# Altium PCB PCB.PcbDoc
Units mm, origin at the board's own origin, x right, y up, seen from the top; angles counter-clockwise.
Board outline 43.18 x 17.78 mm, 4 copper layers (TOP, GND, SIG, BOTTOM), stack 1.586 mm thick; 58 components, 50 nets, 295 pads, 112 vias.
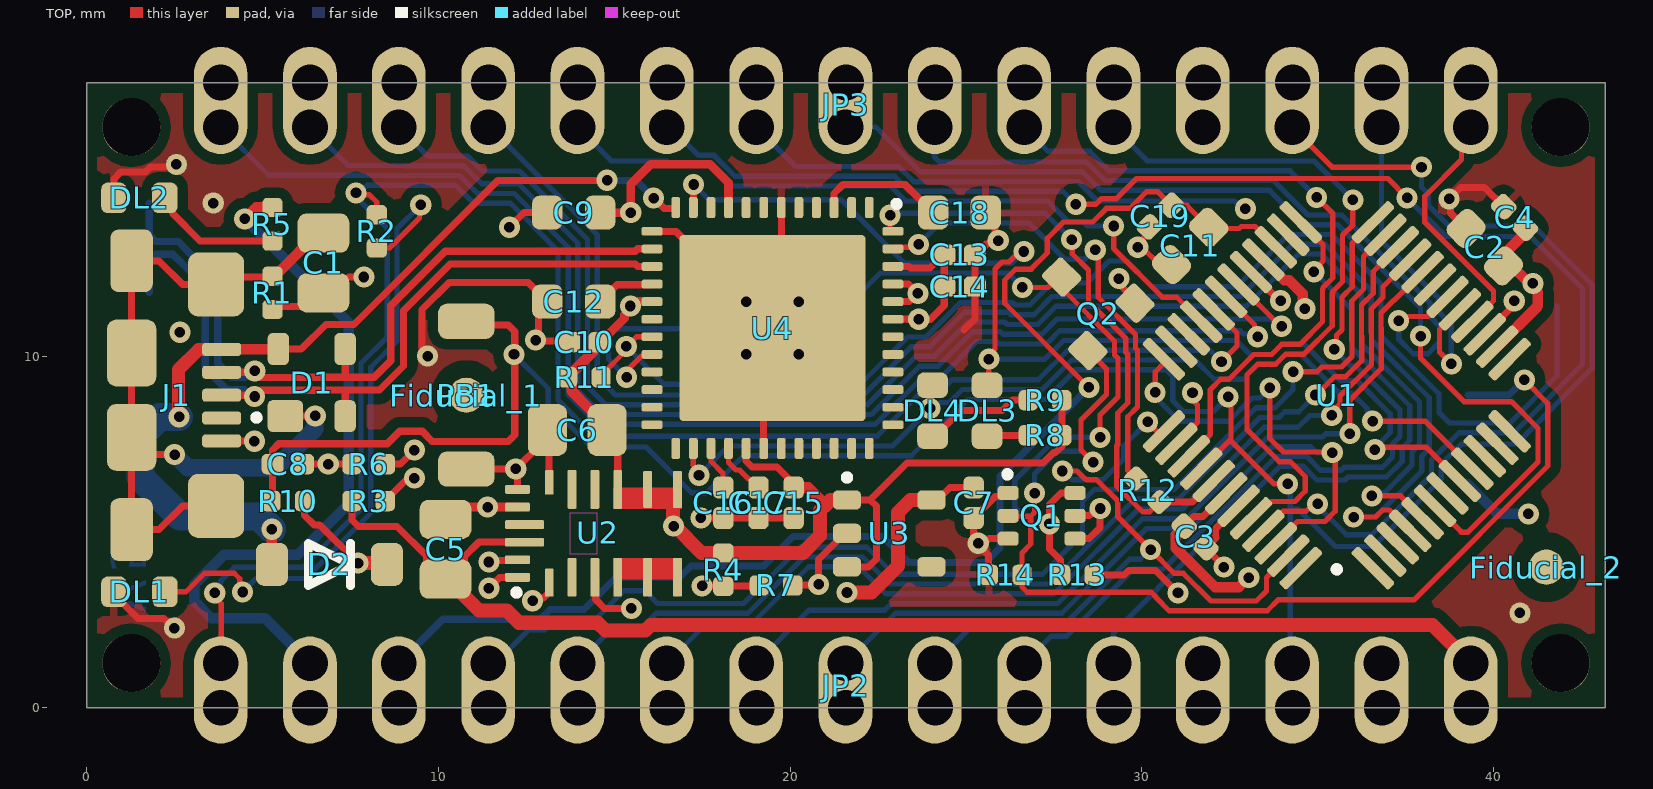
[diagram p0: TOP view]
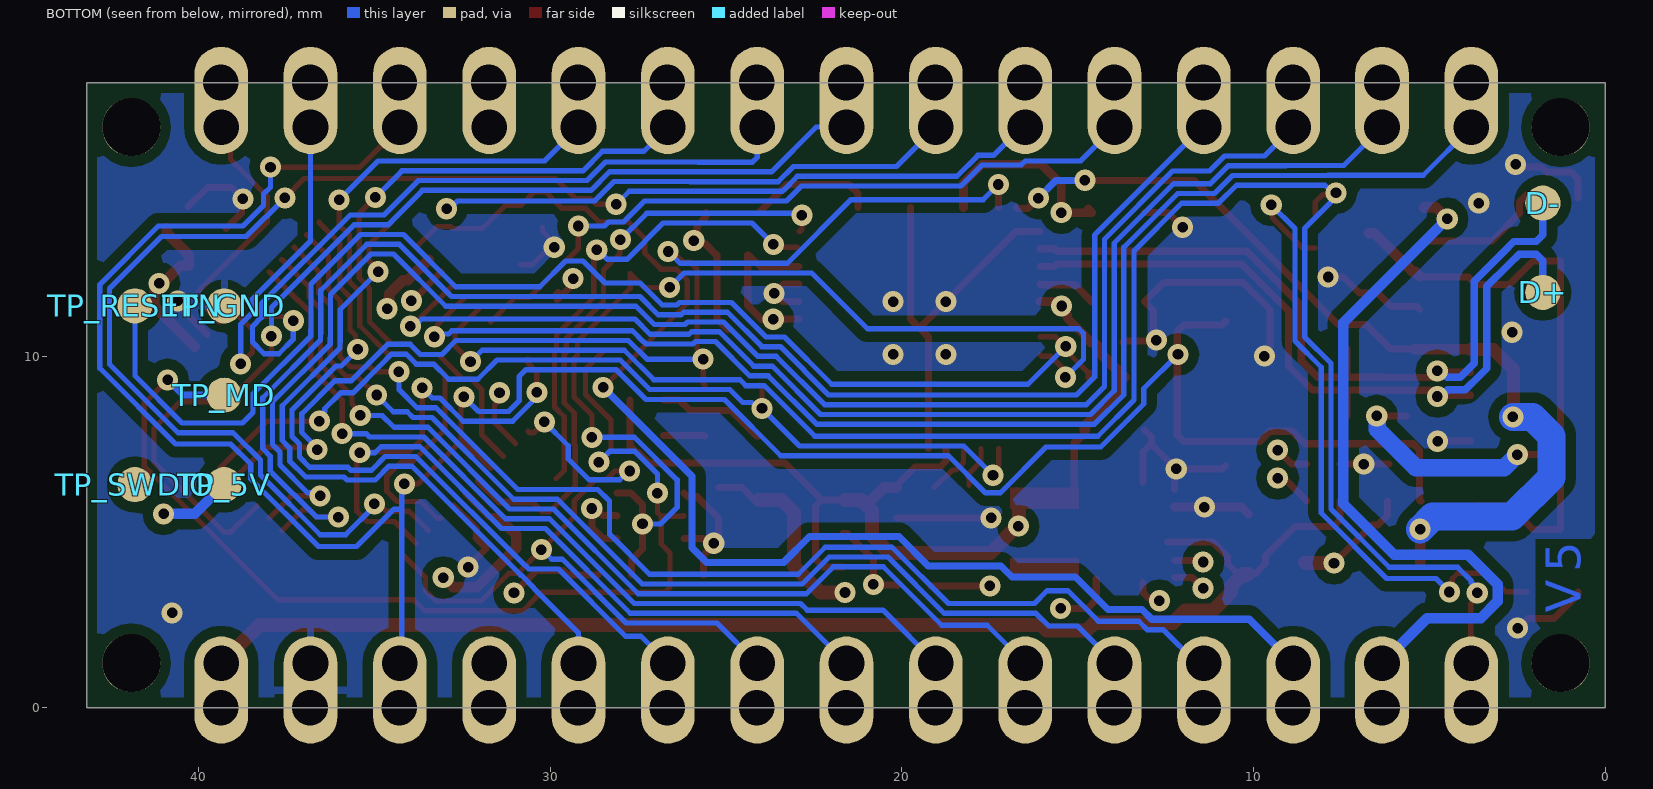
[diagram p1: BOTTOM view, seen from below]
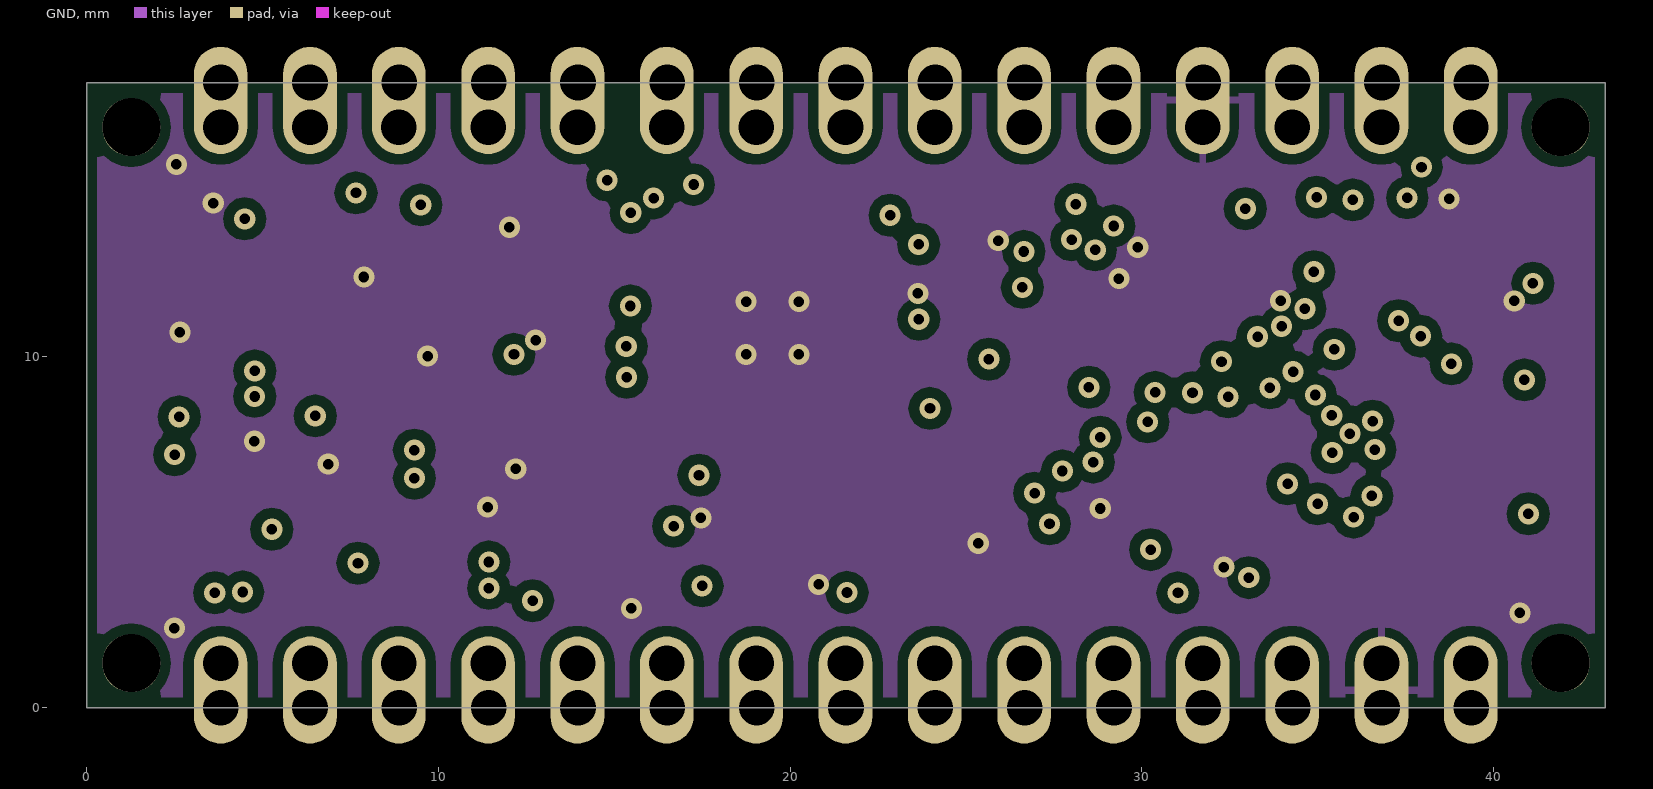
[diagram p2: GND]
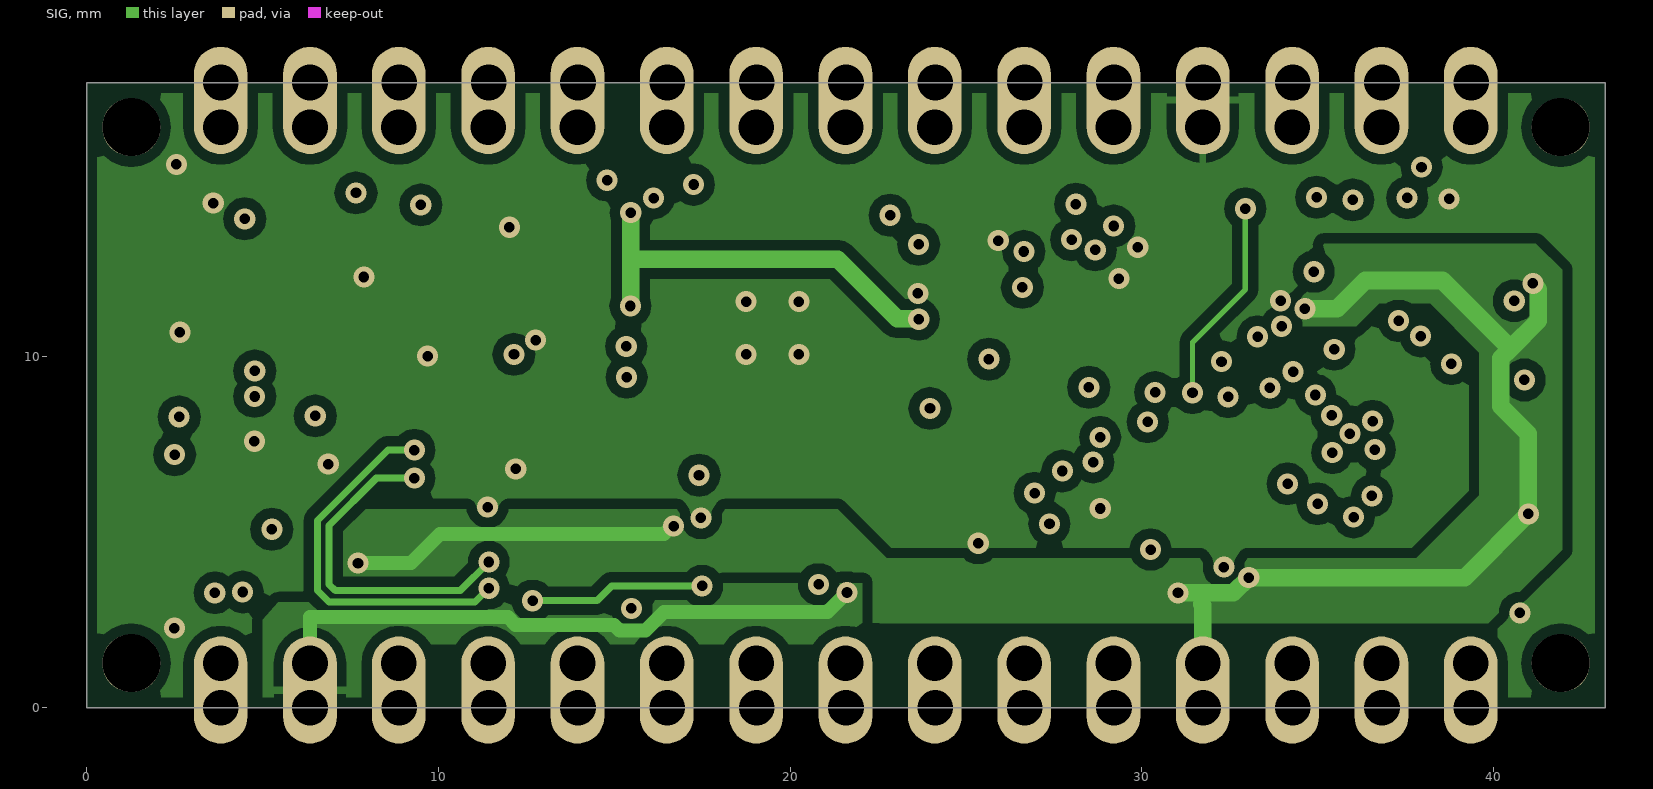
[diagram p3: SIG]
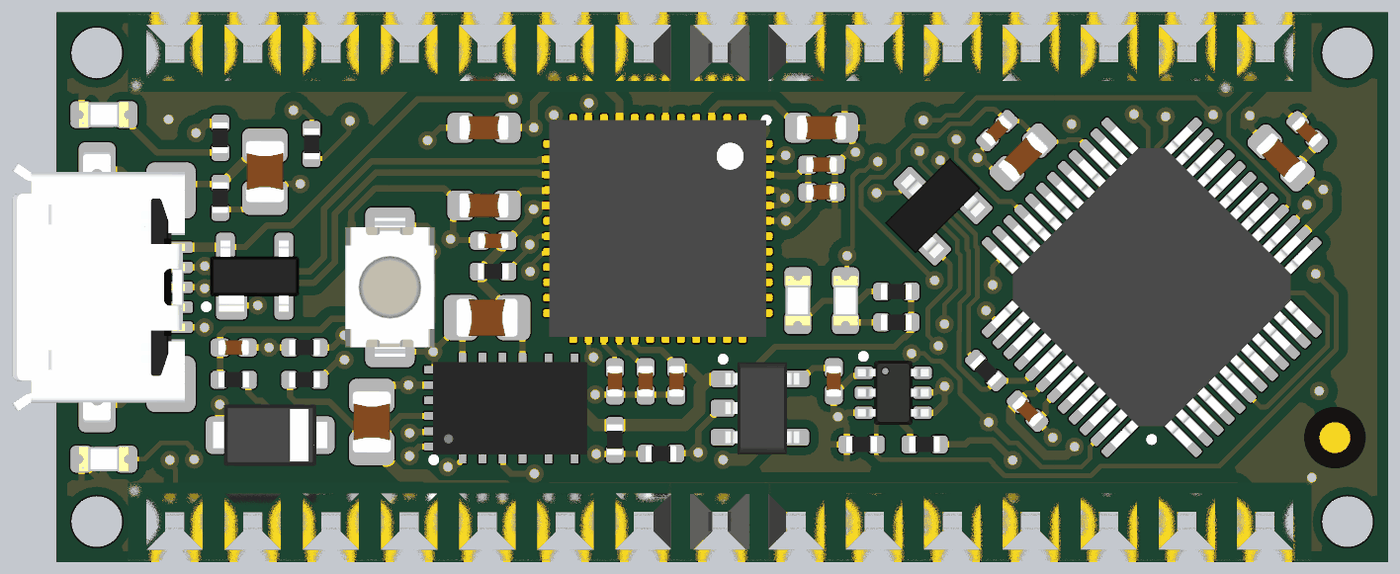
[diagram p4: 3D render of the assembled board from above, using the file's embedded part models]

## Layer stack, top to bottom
Top Solder: solder mask 0.0102, Solder Resist, Dk 3.5
TOP: signal copper 0.018
Dielectric 1: prepreg 0.14, PP-014, Dk 4.2
GND: signal copper 0.035
Dielectric2: core 1.2, FR-4, Dk 4.8
SIG: signal copper 0.035
Dielectric3: prepreg 0.14, PP-014, Dk 4.2
BOTTOM: signal copper 0.018
Bottom Solder: solder mask 0.0102, Solder Resist, Dk 3.5

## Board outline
0,0 43.18,0 43.18,17.78 0,17.78

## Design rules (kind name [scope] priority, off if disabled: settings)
BoardOutlineClearance HeadersCastellated [((ObjectKind = 'Pad') And (Component = 'JP2')) OR                                                                                    ((ObjectKind = 'Pad') And (Component = 'JP3'))] p1: gap=0 ignorepadtopadclearanceinfootprint=FALSE
BoardOutlineClearance Silks [(OnLayer('Top Overlay') OR OnLayer('Bottom Overlay'))] p2: gap=0 ignorepadtopadclearanceinfootprint=FALSE
BoardOutlineClearance [All] p3: gap=0.3 ignorepadtopadclearanceinfootprint=FALSE
Clearance COPPER_0.3mm [All] p1: gap=0.127 ignorepadtopadclearanceinfootprint=FALSE except(0.3: Arc-Fill Arc-Poly Arc-Region Track-Fill Track-Poly Track-Region SMDPad-Fill SMDPad-Poly SMDPad-Region THPad-Fill THPad-Poly THPad-Region Via-Fill Via-Poly Via-Region Fill-Fill Fill-Poly Fill-Region Poly-Poly Poly-Region Region-Region)
Clearance "Generic clearance 0.15mm" [All] p2: gap=0.15 ignorepadtopadclearanceinfootprint=TRUE
ComponentClearance fiducials [HasFootprint('Fiducial mark 1mm with circle-Footprint-1')] p1: gap=-20 collisioncheckmode=3 verticalgap=-20 showdistances=FALSE
ComponentClearance [All] p2: gap=0.2 collisioncheckmode=3 verticalgap=0 showdistances=TRUE
DiffPairsRouting USB [InDifferentialPairClass('USB')] p1: maxlimit=0.25 minlimit=0.15 mostfreqgap=0.25 toplayer_maxgap=0.15 toplayer_prefgap=0.15 toplayer_minwidth=0.21 toplayer_maxwidth=0.21 toplayer_prefwidth=0.21 midlayer2_mingap=0.25 midlayer2_minwidth=0.15 midlayer2_maxwidth=0.15 midlayer2_prefwidth=0.15 bottomlayer_maxgap=0.15 bottomlayer_prefgap=0.15 bottomlayer_minwidth=0.21 bottomlayer_maxwidth=0.21 bottomlayer_prefwidth=0.21 impedanceprofiledriven=TRUE impedanceprofileid={0EDCC732-50F3-4DDA-8B94-FDD99B063592} impedanceprofilevalue=90.000000 maxuncoupledlength=12.7
Height [All] p1: minheight=0 maxheight=30 prefheight=12.7
HoleSize [All] p1: absolutevalues=TRUE maxlimit=30 minlimit=0.3 maxpercent=80.000 minpercent=20.000
HoleToHoleClearance [All] p1: gap=0.25 allowstackedmicrovias=FALSE
MinimumAnnularRing castellated [(ObjectKind = 'Pad') And (AsMM(HoleDiameter) = 1.016) And (AsMM(PadXSize_AllLayers) = 0.7) And (AsMM(PadYSize_AllLayers) = 0.7)] p1: minimumring=0
MinimumAnnularRing [All] p2: minimumring=0.15
PlaneConnect [All] p1: pad.planeconnectstyle=Relief pad.reliefexpansion=0.508 pad.reliefentries=4 pad.reliefconductorwidth=0.254 pad.reliefairgap=0.254 via.planeconnectstyle=Direct via.reliefexpansion=0.508 via.reliefentries=4 via.reliefconductorwidth=0.254 via.reliefairgap=0.254
PolygonConnect [All] p1: thpad.connectstyle=Relief thpad.reliefconductorwidth=0.2 thpad.reliefentries=4 thpad.polygonreliefangle="90 Angle" thpad.airgapwidth=0.254 smdpad.connectstyle=Relief smdpad.reliefconductorwidth=0.2 smdpad.reliefentries=4 smdpad.polygonreliefangle="90 Angle" smdpad.airgapwidth=0.254 via.connectstyle=Direct via.reliefconductorwidth=0.254 via.reliefentries=4 via.polygonreliefangle="90 Angle" via.airgapwidth=0.254
RoomDefinition TOP [InComponentClass('TOP')] p1: confinementstyle=ConfineIn formatcopy=TRUE lockcomponents=FALSE outline 44.6,2.6 48.6,2.6 48.6,5.6 44.6,5.6
RoutingVias StandardVias [All] p1: holewidth=0.3 width=0.6 viastyle="Through Hole" minholewidth=0.3 minwidth=0.6 maxholewidth=0.3 maxwidth=0.6
SilkToSilkClearance [All] p1: silktosilkclearance=0.2
SilkToSolderMaskClearance [IsPad] p1: minsilkscreentomaskgap=0.15 clearancetoexposedcopper=TRUE
SolderMaskExpansion VIAtented [IsVia] p1: expansion=0.102 istentingtop=TRUE
SolderMaskExpansion [All] p2: expansion=0.05 istentingtop=FALSE
UnConnectedPin [All] p1:
UnRoutedNet [All] p1: checkbadconnections=TRUE
ViasUnderSMD ViasUnderSMD_1 [(ObjectKind = 'Pad') And (Name = 'U4-49')] p1: allowed=TRUE
ViasUnderSMD [All] p2: allowed=FALSE
Width StandardTraces [All] p1: maxlimit=5 minlimit=0.127 preferedwidth=0.15
21 further rules are at their usual default settings.

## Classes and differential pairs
differential pair class USB: USB_D_1
differential pair USB_D_1: +USB_D_1_P -USB_D_1_N

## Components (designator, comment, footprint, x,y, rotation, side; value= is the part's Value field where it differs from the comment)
C1 "FV21X472K102ECG" CAP-0805 6.733,12.65 r90 top value=4.7nF
C2 "GRM188R61C475KAAJD" CAP-0603 39.752,13.097 r315 top value=4.7µF
C3 "GRM155R61H104KE19D" CAP-0402 31.514,4.859 r135 top value=100nF
C4 "GRM155R61H104KE19D" CAP-0402 40.601,13.946 r315 top value=100nF
C5 "CL21A226MAQNNNE" CAP-0805 10.204,4.51 r270 top value=22µF
C6 "CL21A226MAQNNNE" CAP-0805 13.95,7.9 r0 top value=22µF
C7 "CL05A105KP5NNNC" CAP-0402 25.218,5.83 r90 top value=1µF
C8 "GRM155R61H104KE19D" CAP-0402 5.718,6.93 r180 top value=100nF
C9 "GRM188R61C475KAAJD" CAP-0603 13.85,14.08 r0 top value=4.7µF
C10 "GRM155R61H104KE19D" CAP-0402 14.15,10.4 r0 top value=100nF
C11 "GRM188R61C475KAAJD" CAP-0603 31.373,13.133 r45 top value=4.7µF
C12 "GRM188R61C475KAAJD" CAP-0603 13.85,11.55 r0 top value=4.7µF
C13 "CL05A105KP5NNNC" CAP-0402 24.818,12.88 r180 top value=1µF
C14 "GRM155R61H104KE19D" CAP-0402 24.818,11.98 r180 top value=100nF
C15 "GRM155R61H104KE19D" CAP-0402 20.103,5.83 r90 top value=100nF
C16 "GRM155R61H104KE19D" CAP-0402 18.103,5.83 r90 top value=100nF
C17 "GRM155R61H104KE19D" CAP-0402 19.103,5.83 r90 top value=100nF
C18 "GRM188R61C475KAAJD" CAP-0603 24.818,14.08 r180 top value=4.7µF
C19 "GRM155R61H104KE19D" CAP-0402 30.525,13.981 r45 top value=100nF
D1 "PRTR5V0U2X,215" SOT190P230X110-4N 6.4,9.25 r0 top
D2 "PMEG6020AELRX" SOD123-1 6.903,4.08 r180 top
D+ "CMP-018-0005-A.3" TP-1.00MM#1 1.778,11.811 r180 bottom
D- "CMP-018-0005-A.3" TP-1.00MM#1 1.778,14.351 r180 bottom
DL1 "KPT-1608YC" LEDC1608X80N-AK 1.5,3.3 r0 top
DL2 "HSMG-C190" LEDC1608X80N-AK 1.5,14.5 r0 top
DL3 "KPT-1608YC" LEDC1608X80N-AK 25.6,8.45 r270 top
DL4 "KPT-1608YC" LEDC1608X80N-AK 24.05,8.45 r270 top locked
Fiducial_1 "Fiducial mark 1mm with 2mm solder" "Fiducial mark 1mm with circle-Footprint-1" 10.794,8.89 r90 top
Fiducial_2 "Fiducial mark 1mm with 2mm solder" "Fiducial mark 1mm with circle-Footprint-1" 41.5,4 r90 top
J1 "ZX62-AB-5PA(31)" ZX62-AB-5PA 1.28,8.89 r270 top locked
JP2 "PINHD-1X15-NANO-ANALOG-CASTELLATED" PINHD-1X14_5VF#1 3.81,1.27 r180 top locked
JP3 "PINHD-1X15-NANO-DIGITAL-CASTELLATED" PINHD-1X14_5VF#2 39.37,16.51 r0 top locked
PB1 "IT-1185AP1C-160G-GTR" C&K_PTS820_NO_HOLES-1 10.794,8.89 r90 top
Q1 "BSS138PS" SOT363 27.15,5.46 r270 top
Q2 "2N7002KT1G" SOT23 28.43,11.54 r45 top
R1 "CRCW04021M00FKED" RES-0402 5.283,11.8 r90 top value=1M
R2 "CRCW0402330RJNED" RES-0402 8.25,13.55 r90 top value=330
R3 "CRCW0402100KFKEDC" RES-0402 8.018,5.88 r180 top value=100k
R4 "CRCW0402100KFKEDC" RES-0402 18.103,3.93 r90 top value=100k
R5 "CRCW0402330RJNED" RES-0402 5.283,13.75 r90 top value=330
R6 "CRCW040253K6FKED" RES-0402 8.018,6.93 r0 top value=53.6k
R7 "CRCW040219K1FKEDC" RES-0402 19.603,3.48 r180 top value=19.1k
R8 "CRCW0402330RJNED" RES-0402 27.25,7.75 r0 top value=330
R9 "CRCW0402330RJNED" RES-0402 27.25,8.75 r0 top value=330
R10 "CRCW0402100KFKEDC" RES-0402 5.718,5.88 r0 top value=100k
R11 "CRCW040219K1FKEDC" RES-0402 14.15,9.4 r180 top value=19.1k
R12 "CRCW04020000Z0EDC" RES-0402 30.164,6.186 r315 top value=0
R13 "CRCW040219K1FKEDC" RES-0402 28.168,3.78 r0 top value=19.1k
R14 "CRCW040219K1FKEDC" RES-0402 26.118,3.78 r0 top value=19.1k
TP_5V "CMP-018-0005-A.3" TP-1.00MM#1 39.268,6.35 r90 bottom
TP_GND "CMP-018-0005-A.3" TP-1.00MM#1 39.268,11.43 r90 bottom
TP_MD "CMP-018-0005-A.3" TP-1.00MM#2 37.9,10.05 r90 bottom
TP_RESETN "CMP-018-0005-A.3" TP-1.00MM#1 41.808,11.43 r90 bottom
TP_SWDIO "CMP-018-0005-A.3" TP-1.00MM#1 41.808,6.35 r90 bottom
U1 "ATMEGA4809-AFR" CQFP50P900X900X120-48N 35.545,8.89 r135 top locked
U2 "MPM3610GQV-Z" POWER-LQFN20 14.7,4.96 r90 top locked
U3 "AP2112K-3.3TRG1" SOT25 22.818,4.96 r270 top
U4 "R7FA2A1AB3CNE#AC0" QFN127P600-8N 19.5,10.8 r270 top

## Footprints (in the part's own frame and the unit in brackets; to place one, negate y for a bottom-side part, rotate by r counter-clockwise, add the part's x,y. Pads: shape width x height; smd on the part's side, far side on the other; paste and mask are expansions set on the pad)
C&K_PTS820_NO_HOLES-1 [mm]
  rrect49% 1x1.6 smd mask+0.05: 1(-2.1,0) 2(2.1,0)
  body extent -2.25,-1.45 2.25,1.45, height 2
CAP-0402 [mm] "Chip Capacitor, 2-Leads, Body  0402 (in) 1005 (mm), IPC Medium Density"
  rrect52% 0.63x0.58 smd mask+0.05: 1(-0.435,0) 2(0.435,0)
  body extent -0.5,-0.25 0.5,0.25, height 0.5
CAP-0603 [mm] "Chip Capacitor, Body 0603 imperial,1.6x0.8mm, IPC High Density"
  rrect51% 0.87x0.97 smd mask+0.05: 1(-0.75,0) 2(0.75,0)
  body extent -0.8,-0.4 0.8,0.4, height 0.8
CAP-0805 [mm] "Chip Capacitor, Body 0805 imperial, 2.0x1.2mm, IPC Medium Density"
  rrect45% 1.11x1.47 smd mask+0.05: 1(-0.85,0) 2(0.85,0)
  body extent -1,-0.62 1,0.63, height 1.25
CQFP50P900X900X120-48N [mm] "CQFP, 48-Leads, Body 9,00x9,00mm, Pitch 0,50mm, IPC Medium Density"
  rrect50% 1.5x0.3 smd mask+0.05: 1(-4.2,2.75) 2(-4.2,2.25) 3(-4.2,1.75) 4(-4.2,1.25) 5(-4.2,0.75) 6(-4.2,0.25) 7(-4.2,-0.25) 8(-4.2,-0.75) 9(-4.2,-1.25) 10(-4.2,-1.75) 11(-4.2,-2.25) 12(-4.2,-2.75) 25(4.2,-2.75) 26(4.2,-2.25) 27(4.2,-1.75) 28(4.2,-1.25) 29(4.2,-0.75) 30(4.2,-0.25) 31(4.2,0.25) 32(4.2,0.75) 33(4.2,1.25) 34(4.2,1.75) 35(4.2,2.25) 36(4.2,2.75)
  rrect50% 0.3x1.5 smd mask+0.05: 13(-2.75,-4.2) 14(-2.25,-4.2) 15(-1.75,-4.2) 16(-1.25,-4.2) 17(-0.75,-4.2) 18(-0.25,-4.2) 19(0.25,-4.2) 20(0.75,-4.2) 21(1.25,-4.2) 22(1.75,-4.2) 23(2.25,-4.2) 24(2.75,-4.2) 37(2.75,4.2) 38(2.25,4.2) 39(1.75,4.2) 40(1.25,4.2) 41(0.75,4.2) 42(0.25,4.2) 43(-0.25,4.2) 44(-0.75,4.2) 45(-1.25,4.2) 46(-1.75,4.2) 47(-2.25,4.2) 48(-2.75,4.2)
  silkscreen extent -3.55,3.45 -3.45,3.55, body extent -4.5,-4.5 4.5,4.5, height 1.17
"Fiducial mark 1mm with circle-Footprint-1" [mm]
  round 1 smd paste-10 mask+0.5: 1(0,0)
  TOP pour cut-out: 0,1 0.383,0.924 0.707,0.707 0.924,0.383 1,0 1,0 0.924,-0.383 0.707,-0.707 0.383,-0.924 0,-1 0,-1 -0.383,-0.924 -0.707,-0.707 -0.924,-0.383 -1,0 -1,0 -0.924,0.383 -0.707,0.707 -0.383,0.924 0,1
LEDC1608X80N-AK [mm]
  rrect50% 0.72x0.87 smd mask+0.05: A(0.725,0) C(-0.725,0)
  body extent -0.8,-0.4 0.8,0.4, height 0.79
PINHD-1X14_5VF#1 [mil]
  oval 60x120 hole 40 copper offset 0,30 paste-99999: 1(0,0) 2(-100,0) 3(-199.41,0) 4(-299.41,0) 5(-399.41,0) 6(-499.41,0) 7(-599.41,0) 8(-699.41,0) 9(-799.41,0) 10(-899.41,0) 11(-999.41,0) 12(-1099.41,0) 13(-1199.41,0) 14(-1299.41,0) 15(-1399.41,0)
  round 27.56 hole 40 mask+7.87: 1(0,50) 2(-100,50) 3(-200,50) 4(-300,50) 5(-400,50) 6(-500,50) 7(-600,50) 8(-700,50) 9(-800,50) 10(-900,50) 11(-1000,50) 12(-1100,50) 13(-1200,50) 14(-1300,50) 15(-1400,50)
  body extent -1454,-50 60,50, height 335
PINHD-1X14_5VF#2 [mil]
  oval 60x120 hole 40 copper offset 0,30 paste-99999: 1(-0.59,0) 2(-100.59,0) 3(-200.59,0) 4(-300.59,0) 5(-400.59,0) 6(-500.59,0) 7(-600.59,0) 8(-700.59,0) 9(-800.59,0) 10(-900.59,0) 11(-1000.59,0) 12(-1100.59,0) 13(-1200.59,0) 14(-1300,0) 15(-1400,0)
  round 27.56 hole 40 mask+7.87: 1(0,50) 2(-100,50) 3(-200,50) 4(-300,50) 5(-400,50) 6(-500,50) 7(-600,50) 8(-700,50) 9(-800,50) 10(-900,50) 11(-1000,50) 12(-1100,50) 13(-1200,50) 14(-1300,50) 15(-1400,50)
  body extent -1460,-50 54,50, height 335
POWER-LQFN20 [mm]
  rrect25% 0.8x0.25 smd paste+0 mask+0.05: 1(-1.4,1.55)
  rrect25% 1.1x0.25 smd paste+0 mask+0.05: 2(-1.25,0.9) 3(-1.25,0.25) 4(-1.25,-0.4) 5(-1.25,-1.25) 6(-1.25,-2.1) 9(1.25,-0.4) 10(1.25,0.25) 11(1.25,0.9)
  rrect25% 1.05x0.25 smd paste+0 mask+0.05: 7(1.25,-2.1) 8(1.25,-1.25)
  rrect25% 0.7x0.25 smd paste+0 mask+0.05: 12(1.45,1.55)
  rrect25% 0.25x0.7 smd paste+0 mask+0.05: 13(1.25,2.45) 14(0.75,2.45) 17(-0.75,2.45) 18(-1.25,2.45)
  rrect25% 0.25x1.1 smd paste+0 mask+0.05: 15(0.25,2.25) 16(-0.25,2.25)
  TOP region: -1.3,-0.275 -0.7,-0.275 -0.7,-2.225 -1.3,-2.225
  TOP region: 1.3,-0.275 0.7,-0.275 0.7,-2.225 1.3,-2.225
  TOP keep-out region: -0.575,0.18 0.575,0.18 0.575,0.97 -0.575,0.97
  silkscreen extent -1.73,2.43 -1.63,2.53, body extent -1.5,-2.5 1.5,2.5, height 1.6
QFN127P600-8N [mm]
  rrect50% 0.6x0.25 smd paste-2539.97 mask+0.05: 1(-3.425,2.75) 2(-3.425,2.25) 3(-3.425,1.75) 4(-3.425,1.25) 5(-3.425,0.75) 6(-3.425,0.25) 7(-3.425,-0.25) 8(-3.425,-0.75) 9(-3.425,-1.25) 10(-3.425,-1.75) 11(-3.425,-2.25) 12(-3.425,-2.75) 25(3.425,-2.75) 26(3.425,-2.25) 27(3.425,-1.75) 28(3.425,-1.25) 29(3.425,-0.75) 30(3.425,-0.25) 31(3.425,0.25) 32(3.425,0.75) 33(3.425,1.25) 34(3.425,1.75) 35(3.425,2.25) 36(3.425,2.75)
  rrect50% 0.25x0.6 smd paste-2539.97 mask+0.05: 13(-2.75,-3.425) 14(-2.25,-3.425) 15(-1.75,-3.425) 16(-1.25,-3.425) 17(-0.75,-3.425) 18(-0.25,-3.425) 19(0.25,-3.425) 20(0.75,-3.425) 21(1.25,-3.425) 22(1.75,-3.425) 23(2.25,-3.425) 24(2.75,-3.425) 37(2.75,3.425) 38(2.25,3.425) 39(1.75,3.425) 40(1.25,3.425) 41(0.75,3.425) 42(0.25,3.425) 43(-0.25,3.425) 44(-0.75,3.425) 45(-1.25,3.425) 46(-1.75,3.425) 47(-2.25,3.425) 48(-2.75,3.425)
  rrect5% 5.3x5.3 smd paste-100 mask+0.05: 49(0,0)
  silkscreen extent -3.57,3.48 -3.48,3.57, body extent -3.52,-3.52 3.52,3.52, height 0.8
RES-0402 [mm] "Chip Resistor, 2-Leads, Body  0402 (in) 1005 (mm), IPC Medium Density"
  rrect51% 0.55x0.58 smd mask+0.05: 1(-0.475,0) 2(0.475,0)
  body extent -0.5,-0.25 0.5,0.25, height 0.34
SOD123-1 [mm]
  rrect50% 0.91x1.22 smd: A(1.635,0) C(-1.635,0)
  silkscreen extent -0.6,-0.6 0.6,0.6, body extent -1.85,-1 1.85,1, height 1.2
SOT23 [mm]
  rrect25% 0.8x0.9 smd: 1(-0.95,-1) 2(0.95,-1) 3(0,1)
  body extent -1.5,-1.25 1.5,1.25, height 1.05
SOT25 [mil]
  rrect50% 21.65x31.5 smd mask+1.97: 1(-37.4,-47.24) 2(0,-47.24) 3(37.4,-47.24) 4(37.4,47.24) 5(-37.4,47.24)
  silkscreen extent -65,-49 -61,-45, body extent -59,-44 59,50, height 43
SOT190P230X110-4N [mm]
  rrect33% 1.01x0.91 smd paste+0 mask+0.05: 1(-0.75,-0.955)
  rrect49% 0.61x0.91 smd paste+0 mask+0.05: 2(0.95,-0.955) 3(0.95,0.955) 4(-0.95,0.955)
  silkscreen extent -1.62,-1.05 -1.52,-0.95, body extent -1.45,-1.15 1.45,1.15, height 1
SOT363 [mm]
  rrect50% 0.4x0.6 smd mask+0.05: 1(-0.65,-0.95) 2(0,-0.95) 3(0.65,-0.95) 4(0.65,0.95) 5(0,0.95) 6(-0.65,0.95)
  silkscreen extent -1.23,-1.02 -1.13,-0.92, body extent -1.05,-1.15 1.05,1.15, height 1
TP-1.00MM#1 [mm]
  rrect100% 1x1 smd paste-2.54 mask+0.05: X(0,0)
TP-1.00MM#2 [mm]
  rrect100% 1x1 smd paste-2.54 mask+0.05: X(-1.16,1.368)
ZX62-AB-5PA [mm]
  rrect49% 0.37x1.11 smd paste+0 mask+0.05: 1(-1.3,2.56) 2(-0.65,2.56) 3(0,2.56) 4(0.65,2.56) 5(1.3,2.56)
  rrect37% 1.825x1.6 smd paste+0 mask+0.05: M1(-3.147,2.4) M4(3.147,2.4)
  rrect37% 1.78x1.2 smd paste+0 mask+0.05: M2(-3.82,0) M3(3.82,0)
  rrect37% 1.9x1.4 smd paste+0 mask+0.05: M5(-1.2,0) M6(1.2,0)
  body extent -4.4,-2.75 4.4,2.85, height 2.75

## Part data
C1: library part C0059-A.14, "CAP CHIP 0805 4.7nF 10% 1000V X7R", Case Code (Imperial)=0805, Dielectric=X7R, Manufacturer="PSA Shenzen", Manufacturer 2=KEMET, Part number 2=C0805V472KDRACTU, Part number 3=C0805C472KDRACTU, Tolerance=10%, Voltage=1kV
C2 C9 C11 C12 C18: library part C0054-A.16, "CAP CHIP 0603 4.7uF 10% 16V X5R", Case Code (Imperial)=0603, Dielectric=X5R, Manufacturer=Murata, Manufacturer 3="Samsung Electro-Mechanics", Part number 2=GRM188R61C475KE11D, Part number 3=CL10A475KO8NNNC, Tolerance=10%, Voltage=16V
C3 C4 C8 C10 C14 C15 C16 C17 C19: library part C0015-A.14, "CAP CHIP 0402 100nF 10% 50V X5R", Case Code (Imperial)=0402, Dielectric=X5R, Manufacturer=Murata, Tolerance=10%, Voltage=50V
C5 C6: library part C0111-A.7, "CAP CHIP 0805 22uF 20% 25V X5R", Case Code (Imperial)=0805, Dielectric=X5R, Manufacturer="Samsung Electro-Mechanics", Tolerance=20%, Voltage=25V
C7 C13: library part C0017-A.14, "CAP CHIP 0402 1uF 10% 10V X5R", Case Code (Imperial)=0402, Dielectric=X5R, Manufacturer="Samsung Electro-Mechanics", Manufacturer 2="Murata Electronics", Part number 2=GCM155C71A105KE38D, Tolerance=10%, Voltage=10V
D1: library part D0025-A.5, "TVS ARRAY 4LIN.8kV 1pF SOT143B", Manufacturer=Nexperia
D2: library part D0026-A.6, "DIODE SCHOTTKY SMD 2A 60V SOD123FL", Forward Current=2A, Forward Voltage=0.6V, Manucturer Part Number 2=SS26L, Manufacturer=Nexperia
D+ D- TP_5V TP_GND TP_MD TP_RESETN TP_SWDIO: library part UT0013-A.4, "Test point 1.00mm"
DL1 DL3 DL4: library part L0008-A.5, "LED SMD 0603 GIA588   8mcd 120^", Manufacturer=Kingbright
DL2: library part L0009-A.5, "LED SMD 0603 GREEN/568 15mcd 120^", Manufacturer=Broadcom
Fiducial_1 Fiducial_2: library part UT0024-A.6
J1: library part J0039-A.7, "CONN USB MICRO F/90^ SMD TipoAB 5x1", Manufacturer=Hirose
JP2: library part J0158-A.4, "CONN THD SOCKET F/1/D 15V JANALOG NANO-TYPE CASTELLATED"
JP3: library part J0183-A.4, "CONN THD SOCKET F/1/D 15V JDIGITAL NANO-TYPE CASTELLATED"
PB1: library part B0001-A.7, "PUSHBUTTON WHITE NO ANCHORS", Color=White, Manufacturer=Switronic
Q1: library part T0012-A.8, "MOSFET N-CH 2x 60V 0.32A SOT363", Manufacturer=Nexperia
Q2: library part T0004-A.9, "MOSFET N-CH 60V 300mA ESD prot. SOT23", Manufacturer="On Semiconductor", Manufacturer 2=Hottech, Manufacturer Part Number 2=2N7002K
R1: library part R0058-A.24, "RES CHIP 0402 1M 1% 1/16W", Case Code (Imperial)=0402, Manufacturer=Vishay, Power=62.5mW, Temperature Coefficient=100ppm, Tolerance=1%
R2 R5 R8 R9: library part R0017-A.24, "RES CHIP 0402 330R 5% 1/16W", Case Code (Imperial)=0402, Manufacturer=Vishay, Power=62.5mW, Temperature Coefficient=200ppm, Tolerance=5%
R3 R4 R10: library part R0001-A.24, "RES CHIP 0402 100K 1% 1/16W", Case Code (Imperial)=0402, Manufacturer=Vishay, Power=62.5mW, Temperature Coefficient=100ppm, Tolerance=1%
R6: library part R0050-A.24, "RES CHIP 0402 53k6 1% 1/16W", Case Code (Imperial)=0402, Manufacturer=Vishay, Power=62.5mW, Temperature Coefficient=100ppm, Tolerance=1%
R7 R11 R13 R14: library part R0033-A.24, "RES CHIP 0402 19k1 1% 1/16W", Case Code (Imperial)=0402, Manufacturer=Vishay, Power=62.5mW, Temperature Coefficient=100ppm, Tolerance=1%
R12: library part R0000-A.24, "RES CHIP 0402 0R 1/16W", Case Code (Imperial)=0402, Manufacturer=Vishay, Power=62.5mW, Temperature Coefficient=0ppm, Tolerance=0%
U1: library part U0039-A.7, Manufacturer=Microchip
U2: library part U0075-A.13, "IC Buck with integrated inductor 4.5 to 21V max 1.2A QFN20 3x5x1.6mm", Manufacturer=MPS
U3: library part U0027-A.11, "IC LDO Vin max 6.5V Vout 3V3 Iout 600mA +EN  SOT25", Manufacturer="Diodes Inc"
U4: library part U0258-A.7, "IC uC 32b 256k +8k flash 32k RAM 1V8 to 5.5V QFN48", Manufacturer=Renesas

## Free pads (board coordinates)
  round 1.651 hole 1.651 unplated: MH(1.27,1.27) MH(1.27,16.51) MH(41.91,1.27) MH(41.91,16.51)

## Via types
v1: diameter 0.6, hole 0.3, TOP to BOTTOM, tented both sides, 112 vias

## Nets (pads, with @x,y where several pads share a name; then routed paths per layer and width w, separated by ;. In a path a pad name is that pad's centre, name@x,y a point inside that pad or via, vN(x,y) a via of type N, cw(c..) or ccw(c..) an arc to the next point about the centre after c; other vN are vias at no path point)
+3V3: C7.2 JP2.2 R5.2 U3.5 | length 42.9
  TOP w0.2: U3.5@24.068,5.91 24.189,5.91 24.544,6.265 C7.2
  TOP w0.3: v1(4.495,13.904) 4.819,14.228 5.143,14.228 5.146,14.225 R5.2@5.15,14.225
  TOP w0.4: v1(21.618,3.28) 22.318,3.28 23.068,4.03 23.068,5.558 23.42,5.91 U3.5@24.068,5.91
  SIG w0.4: JP2.2@6.35,1.27 6.35,2.58 11.975,2.58 12.196,2.359 14.998,2.359 15.157,2.2 15.885,2.2 16.415,2.73 21.068,2.73 v1(21.618,3.28)
  BOTTOM w0.3: v1(4.495,13.904) 7.45,10.949 7.45,5.8 6,4.35 3.905,4.35 3.066,3.51 3.066,3.032 3.548,2.55 5.07,2.55 JP2.2@6.35,1.27
+5V: C2.2 C3.2 C4.2 C6.2 C9.2 C10.2 C13.2 C14.2 C15.2 D2.C JP2.12 R4.2 R8.2 R9.2 R10.2 R11.2 R13.2 TP_5V.X U1.14 U1.28 U1.42 U2.7 U2.8 U2.9 U3.1 U3.3 U4.9 U4.17 U4.29 U4.43 U4.46 | length 105.6
  TOP w0.15: 16.668,5.753 16.693,5.753 16.75,5.81 U2.7@16.75,6.21 ; 20.993,5.782 21.029,5.782
  TOP w0.2: R10.2 6.193,5.471 6.46,5.205 6.623,5.205 v1(7.715,4.113) ; C6.2@14.8,7.8 C6.2@15.05,7.55 ; U2.9 C6.2@15.1,7.55 ; U4.29 18.75,7.019 18.921,6.848 19.623,6.848 C15.2@20.18,6.291 ; U3.1 22.278,5.91 ; U3.3@21.669,4.01 22.233,4.01 22.453,4.23 22.453,5.734 22.278,5.91 ; U4.43 23.33,11.05 ; U4.46 23.376,12.55 23.423,12.503 23.981,12.503 24.358,12.88 C13.2 C14.2 24.383,11.445 23.988,11.049 v1(23.659,11.049) 23.331,11.049 ; R9.2 27.725,7.438 27.549,7.262 27.491,7.262 27.186,6.957 23.325,6.957 22.278,5.91 ; R13.2 29.495,3.78 29.624,3.909 30.387,3.909 v1(31.029,3.267) ; C3.2 31.479,5.439 31.74,5.439 U1.42
  TOP w0.25: C10.2@14.61,10.4 15.296,11.086 15.296,11.166 15.462,11.332 v1@15.462,11.384 ; C9.2@14.7,14.18 C9.2 v1(15.47,14.08) 15.47,14.89 16.037,15.457 17.722,15.457 18.25,14.929 U4.9 ; v1(15.462,11.427) v1@15.462,11.384 ; v1@15.486,11.361 v1@15.462,11.384 ; v1@15.675,11.55 U4.17
  TOP w0.3: C10.2@14.61,10.4 C10.2 14.56,10.4 14.42,10.26 14.42,10.145 13.84,9.565 13.825,9.565 13.675,9.415 R11.2 13.789,9.286 13.789,9.01 14.264,8.535 14.8,7.999 C6.2 ; C15.2@20.153,6.265 20.51,6.265 20.993,5.782 ; C3.2@31.207,5.153 30.971,4.917 30.971,4.544 32.088,3.426 32.754,3.426 33.033,3.705 v1(33.041,3.705) ; U1.28 34.049,12.153 34.186,12.153 34.573,11.766 v1@34.573,11.603 ; U1.14 41.264,11.427 v1@41.264,11.822 ; C4.2 40.908,13.506 40.283,12.88 C2.2 40.519,12.567 v1@41.069,12.017
  TOP w0.4: v1(7.715,4.113) 7.723,4.122 8.53,4.122 D2.C@8.538,4.13 ; 16.668,5.753 16.668,5.188 v1(16.689,5.166) 16.726,5.166 17.487,4.405 20.361,4.405 20.853,4.897 20.853,5.606 21.029,5.782 21.157,5.91 U3.1
  SIG w0.4: v1(7.715,4.113) 7.725,4.124 9.222,4.124 10.041,4.944 16.413,4.944 16.635,5.166 v1(16.689,5.166)
  SIG w0.5: v1(15.462,11.427) 15.466,11.431 15.466,12.753 ; v1(15.47,14.08) 15.466,14.076 15.466,12.753 ; v1(23.659,11.049) 23.64,11.068 23.044,11.068 21.359,12.753 15.466,12.753 ; v1(31.029,3.267) 32.604,3.267 v1(33.041,3.705) 39.177,3.705 v1(40.99,5.517) 40.99,7.791 40.2,8.58 40.2,9.936 40.482,10.218 ; 31.7,2.95 31.735,2.915 JP2.12@31.735,1.27 ; v1(34.637,11.349) 35.549,11.349 36.35,12.15 38.55,12.15 40.482,10.218 ; v1(41.121,12.07) 41.121,12.043 41.268,11.896 41.268,11.003 40.482,10.218
  BOTTOM w0.3: TP_5V.X 40.101,5.517 v1(40.99,5.517)
AREF_1: C11.2 C19.2 JP2.3 U1.27 | length 38.4
  TOP w0.15: v1(28.493,9.113) 26.104,11.503 26.104,12.162 26.416,12.474 26.854,12.474 27.312,12.932 27.312,13.35 27.777,13.815 28.605,13.815 28.992,14.202 29.666,14.202 30.143,14.678 30.443,14.678 C19.2 30.834,14.287 31.279,14.287 C11.2 31.939,13.628 32.77,13.628 32.829,13.687 33.223,13.687 U1.27
  BOTTOM w0.2: JP2.3@8.875,1.27 10.124,2.519 12.897,2.519 13.171,2.794 14.137,2.794 15.063,3.72 16.87,3.72 17.187,4.037 19.253,4.037 20.085,4.869 22.629,4.869 23.36,4.139 25.554,4.139 25.967,4.551 25.967,6.586 v1(28.493,9.113)
GND: C1.1 C2.1 C3.1 C4.1 C5.1 C6.1 C7.1 C8.1 C9.1 C10.1 C11.1 C12.1 C13.1 C14.1 C15.1 C16.1 C17.1 C18.1 C19.1 DL1.C DL2.C J1.5 JP2.14 JP3.4 PB1.1 Q1.1 Q1.3 Q1.4 Q1.5 Q2.2 R1.1 R6.1 R7.1 R14.1 TP_GND.X U1.15 U1.29 U1.43 U2.3 U2.12 U2.13 U2.14 U3.2 U4.6 U4.13 U4.30 U4.44 U4.45 U4.49 | length 66.9
  TOP w0.15: Q2.2@29.773,11.84 Q2.2@29.909,11.705 ; v1@29.885,12.975 v1(29.885,13.096) ; C19.1 30.217,13.551 29.885,13.218 v1(29.885,13.096) ; C11.1 30.5,12.602 30.006,13.096 v1(29.885,13.096)
  TOP w0.2: DL1.C 0.775,3.225 1.456,2.544 2.202,2.544 2.477,2.269 v1(2.493,2.269) ; DL2.C 0.775,15.035 0.982,15.242 1.676,15.242 1.811,15.377 2.477,15.377 v1(2.55,15.45) ; J1.5 4.758,7.59 v1(4.768,7.58) ; R1.1 5.376,11.418 6.09,11.418 6.472,11.8 6.994,11.8 7.444,12.25 v1(7.882,12.25) ; C8.1 v1(6.868,6.93) R6.1 ; v1(9.693,10) 9.693,10.109 9.537,10.265 9.537,11.324 10.312,12.1 12.55,12.1 C12.1 12.843,11.293 12.843,10.53 v1(12.767,10.454) 12.793,10.427 13.688,10.427 C10.1 ; PB1.1@10.794,6.89 10.891,6.794 v1@12.2,6.794 ; v1(12.018,13.665) 12.433,14.08 C9.1 ; U2.13 v1@12.251,6.793 ; C6.1 12.899,7.699 C6.1@12.899,7.492 ; U2.12 13.15,7.276 12.935,7.492 C6.1@12.899,7.492 ; U2.3@14.475,3.66 14.475,3.078 14.726,2.827 v1(15.489,2.827) ; U4.13 16.75,13.55 v1(18.75,11.55) U4.49 ; v1(17.466,5.4) 17.471,5.395 C16.1 C17.1 C15.1 C15.1@20.153,5.395 ; U4.30 19.25,10.55 U4.49 ; U4.6 19.75,11.05 U4.49 ; R7.1@20.128,3.48 20.144,3.495 20.796,3.495 v1(20.811,3.511) 20.811,4.222 21.549,4.96 U3.2 U3.2@21.669,4.96 ; U4.44 23.399,11.55 v1(23.636,11.786) 23.372,12.05 U4.45 ; 24.95,10.75 25.253,11.053 C14.1 C13.1 25.278,12.88 25.607,13.209 25.844,13.209 v1(25.92,13.285) 25.844,13.362 25.844,13.512 25.828,13.528 25.828,13.704 25.568,13.964 C18.1 ; v1@25.415,4.568 25.643,4.339 R14.1 ; Q1.3 25.657,4.81 25.477,4.63 25.403,4.63 v1(25.352,4.681) 25.352,4.755 25.218,4.888 C7.1 25.833,6.01 26.1,6.01 Q1.1 ; Q1.4 28.5,4.81 28.818,5.128 28.818,5.484 28.846,5.512 28.854,5.512 28.854,5.633 v1(28.818,5.669) ; Q1.5 28.109,5.469 28.51,5.469 28.633,5.592 28.748,5.592 v1@28.818,5.523 ; v1(29.347,12.203) 29.414,12.136 29.414,11.999 Q2.2@29.809,11.605 ; v1(32.334,4.003) 32.334,4.022 31.822,4.533 C3.1 32.107,4.836 32.1,4.843 32.1,5.092 U1.43 ; U1.29 33.919,11.576 v1(33.947,11.576) ; C2.1 38.778,14.071 38.778,14.429 v1(38.736,14.471) 39.065,14.8 39.747,14.8 C4.1 ; U1.15 40.423,11.294 40.423,11.296 40.591,11.464 v1(40.591,11.572) ; v1(12.201,6.793) C6.1@12.899,7.492 ; v1@12.2,6.794 v1(12.201,6.793)
  TOP w0.25: C5.1@10.144,5.51 10.344,5.71 v1(11.4,5.71) ; v1@11.45,5.71 U2.14
  other v1: 40.75,2.7 18.75,10.05 20.25,10.05 2.653,10.68 20.25,11.55 3.6,14.35
NetC1_2: C1.2 D1.1 J1.M1 J1.M2 J1.M3 J1.M4 J1.M5 J1.M6 R1.2 | length 23.9
  TOP w0.2: v1(2.5,7.2) 1.77,7.2 J1.M6 ; J1.M4 2.733,5.742 2.06,5.07 J1.M3 J1.M6 ; R1.2 5.258,12.25 3.892,12.25 J1.M1 2.733,12.037 2.06,12.71 J1.M2 J1.M5 J1.M6 ; D1.1 6.495,8.295 v1(6.5,8.3)
  TOP w0.3: R1.2 5.408,12.4 5.471,12.4 6.571,13.5 C1.2
  BOTTOM w0.5: v1(2.5,7.2) 2.872,6.828 5.384,6.828 6.481,7.924 6.481,8.281 v1(6.5,8.3)
NetC12_2: C12.2 U4.16 | length 1.7
  TOP w0.21: C12.2 15.08,12.03 16.055,12.03 U4.16
NetC16_2: C16.2 U4.27 | length 1.2
  TOP w0.15: U4.27 17.75,7.011 18.095,6.666 C16.2@18.095,6.323
NetC17_2: C17.2 U4.28 | length 1.5
  TOP w0.15: U4.28 18.25,6.975 18.462,6.763 18.565,6.763 18.823,6.505 18.847,6.505 19.087,6.265 C17.2
NetC18_2: C18.2 U4.3 | length 3.7
  TOP w0.2: U4.3 21.25,14.625 21.499,14.874 23.275,14.874 C18.2
NetDL1_A: DL1.A R2.1 | length 18.7
  TOP w0.15: DL1.A 2.824,3.3 3.35,3.826 4.196,3.826 4.352,3.669 4.352,3.375 v1(4.433,3.294) ; R2.1 8.615,13.075 9.465,13.925 9.465,14.265 v1(9.5,14.3)
  BOTTOM w0.15: v1(4.433,3.294) 4.818,3.68 6.22,3.68 8.079,5.539 8.079,9.683 8.827,10.431 8.827,13.627 v1(9.5,14.3)
NetDL2_A: DL2.A R5.1 | length 3.7
  TOP w0.2: DL2.A@2.225,14.6 2.436,14.389 2.436,14.064 3.225,13.275 R5.1@5.15,13.275
NetDL3_A: DL3.A R8.1 | length 1.2
  TOP w0.2: DL3.A 25.625,7.75 R8.1
NetDL4_A: DL4.A R9.1 | length 3.1
  TOP w0.2: DL4.A 24.138,7.725 24.863,8.45 26.03,8.45 26.33,8.75 R9.1
NetQ1_2: Q1.2 Q2.1 R14.2 TP_MD.X | length 31.4
  TOP w0.15: Q1.2 26.211,5.449 26.845,5.449 ; v1(26.952,6.104) 26.952,5.557 26.845,5.449 ; Q2.1 28.995,9.631 28.995,8.905 28.273,8.183 28.273,7.331 v1(28.616,6.988) ; v1(40.877,9.324) 41.544,8.657 41.544,6.875 37.739,3.07 33.878,3.07 33.568,2.761 30.774,2.761 30.4,3.135 30.4,3.156 30.268,3.288 26.743,3.288 26.593,3.437 R14.2 26.593,4.406 26.845,4.658 26.845,5.449
  BOTTOM w0.15: v1(26.952,6.104) 26.952,6.652 27.593,7.293 28.311,7.293 v1(28.616,6.988)
  BOTTOM w0.2: TP_MD.X 40.444,8.89 v1(40.877,9.324)
NetR3_1: R3.1 U2.17 | length 11.5
  TOP w0.2: R3.1 8.493,5.895 9.052,6.453 9.242,6.453 v1(9.318,6.53) ; v1(11.436,4.147) v1@11.474,4.185 ; v1@11.524,4.185 12.226,4.185 U2.17
  SIG w0.2: v1(9.318,6.53) 8.233,6.53 6.894,5.19 6.894,3.51 7.07,3.334 10.623,3.334 v1(11.436,4.147)
NetR4_1: R4.1 R7.2 U2.1 | length 7.5
  TOP w0.2: v1(12.679,3.046) 12.755,3.123 12.988,3.123 13.15,3.285 U2.1 ; v1(17.499,3.466) 19.165,3.466 R7.2@19.178,3.48
  SIG w0.2: v1(12.679,3.046) 14.509,3.046 14.929,3.466 ; 14.979,3.466 v1(17.499,3.466)
NetR6_2: R6.2 U2.18 | length 12.6
  TOP w0.2: R6.2 8.918,6.93 v1(9.318,7.33) ; v1(11.436,3.402) 11.744,3.71 ; 11.794,3.71 U2.18
  SIG w0.2: v1(9.318,7.33) 8.571,7.33 6.567,5.326 6.567,3.335 6.895,3.007 11.041,3.007 v1(11.436,3.402)
NetR12_1: R12.1 U4.47 | length 13.8
  TOP w0.15: U4.47 22.975,13.1 23.574,13.1 v1(23.653,13.179) ; v1(28.676,13.019) 28.761,12.934 28.761,11.674 29.823,10.612 29.823,10.225 29.879,10.169 29.879,8.553 29.601,8.275 29.601,6.749 R12.1
  BOTTOM w0.15: v1(23.653,13.179) 24.262,13.787 26.788,13.787 27.822,12.753 28.376,12.753 28.642,13.019 v1(28.676,13.019)
PA00_1: JP3.5 U1.44 | length 20.5
  TOP w0.15: U1.44 33.212,5.39 33.689,5.868 34.355,5.868 34.649,6.162 34.649,6.578 34.229,6.998 33.91,6.998 32.994,7.915 32.994,9.47 33.296,9.773 33.808,9.773 34.093,10.058 34.611,10.058 35.416,10.863 35.416,11.789 35.429,11.802 35.429,11.836 35.708,12.115 35.708,13.44 36.001,13.733 v1(36.001,14.44)
  BOTTOM w0.15: JP3.5@29.195,16.51 30.159,15.546 34.895,15.546 v1(36.001,14.44)
PA01_1: JP3.10 U1.45 | length 42.7
  TOP w0.15: v1(28.125,14.318) 28.697,14.318 28.858,14.479 29.279,14.479 29.85,15.05 36.996,15.05 v1(37.546,14.5) ; U1.45 34.013,5.591 34.669,5.591 34.878,5.8 v1(35,5.8)
  BOTTOM w0.15: JP3.10@16.495,16.51 16.598,16.51 17.399,15.709 17.841,15.709 18.436,15.114 22.972,15.114 23.358,14.729 23.401,14.685 26.139,14.685 26.143,14.69 27.753,14.69 v1(28.125,14.318) ; v1(35,5.8) 35,5.739 35.815,4.924 36.54,4.924 38.239,6.623 38.239,7.046 39.016,7.823 40.581,7.823 42.528,9.77 42.528,11.923 41.051,13.4 38.646,13.4 v1(37.546,14.5)
PA02_1: JP2.8 U1.36 U1.46 | length 28.7
  TOP w0.15: v1(30.381,8.968) 30.381,9.553 30.634,9.806 30.634,9.912 U1.36 ; v1(33.64,9.096) 33.64,7.66 34.025,7.275 35.397,7.275 35.502,7.17 35.502,5.592 35.208,5.298 34.428,5.298 U1.46
  BOTTOM w0.15: JP2.8@21.575,1.27 22.996,2.691 27.726,2.691 30.135,5.1 31.381,5.1 33.707,7.426 34.809,7.426 34.979,7.255 v1(35.417,7.255) ; v1(30.381,8.968) 30.467,8.882 30.467,8.75 31.067,8.15 32.472,8.15 33.133,8.811 33.354,8.811 v1(33.64,9.096)
PA03_1: JP2.9 U1.37 U1.47 | length 20.5
  TOP w0.15: v1(27.745,6.735) 28.16,6.735 28.383,6.512 28.399,6.512 28.425,6.486 28.711,6.486 29.32,5.877 29.32,5.43 v1(30.25,4.5) 30.925,3.825 31.18,3.825 31.968,3.038 33.254,3.038 33.543,3.328 33.543,3.706 U1.47 ; v1(30.166,8.13) 30.478,7.818 30.584,7.818 U1.37
  BOTTOM w0.15: JP2.9@24.115,1.27 25.259,2.414 27.841,2.414 29.653,4.227 29.957,4.227 30.23,4.5 v1(30.25,4.5) ; v1(27.745,6.735) 27.778,6.735 28.026,6.486 28.897,6.486 29.489,7.078 29.489,7.453 v1(30.166,8.13)
PB00_1: JP3.12 U1.4 | length 43.3
  TOP w0.15: v1(36.023,5.426) 36.65,5.426 36.853,5.628 37.039,5.628 U1.4
  BOTTOM w0.15: JP3.12@11.415,16.51 11.45,16.51 14.52,13.44 14.52,9.411 15.034,8.898 22.085,8.898 23.457,10.27 23.775,10.27 23.982,10.27 24.959,11.247 26.211,11.247 26.283,11.175 26.929,11.175 27.45,11.697 32.804,11.697 34.287,13.18 35.215,13.18 36.524,11.871 36.524,10.634 36.528,10.63 36.528,10.462 38.173,8.818 38.173,7.371 37.962,7.16 37.962,6.737 36.65,5.426 v1(36.023,5.426)
PB01_1: JP3.13 U1.5 | length 44.2
  TOP w0.15: v1(36.542,6.028) 37.359,6.028 37.985,5.403 U1.5
  BOTTOM w0.15: JP3.13@8.875,16.51 9.692,15.693 10.828,15.693 11.258,15.264 12.305,15.264 14.243,13.325 14.243,9.134 14.757,8.621 22.199,8.621 23.572,9.993 23.89,9.993 24.097,9.993 25.073,10.97 26.097,10.97 26.168,10.898 27.043,10.898 27.565,11.42 32.97,11.42 34.453,12.903 35.101,12.903 36.247,11.756 36.247,10.519 36.251,10.516 36.251,10.348 37.896,8.703 37.896,7.486 37.685,7.275 37.685,6.904 36.895,6.114 36.628,6.114 v1(36.542,6.028)
PB02_1: JP3.8 U1.6 | length 29.1
  TOP w0.15: v1(37.927,10.571) 37.927,9.944 39.165,8.706 40.51,8.706 41.267,7.95 41.267,6.99 39.272,4.996 39.086,4.996 U1.6
  BOTTOM w0.15: JP3.8@21.575,16.51 21.578,16.513 22.437,16.513 23.711,15.239 25.909,15.239 25.914,15.244 28.314,15.244 28.843,14.715 33.635,14.715 34.616,13.734 35.575,13.734 37.927,11.381 v1(37.927,10.571)
PB04(TX3)_1: DL3.C U1.8 U4.11 | length 32.3
  TOP w0.15: DL3.C 25.651,9.226 25.651,10.036 25.827,10.211 25.827,12.482 26.023,12.678 26.228,12.678 26.526,12.976 v1(26.646,12.976) ; v1(36.629,7.341) 36.701,7.413 38.082,7.413 U1.8
  TOP w0.2: U4.11 17.254,14.229 17.254,14.876 v1(17.258,14.88)
  BOTTOM w0.15: v1(17.258,14.88) 17.688,14.45 21.45,14.45 23.258,12.642 26.312,12.642 v1(26.646,12.976) ; v1(25.651,9.914) 27.248,9.914 27.78,10.446 32.686,10.446 33.082,10.05 33.693,10.05 33.978,10.335 34.624,10.335 35.08,9.879 35.08,9.875 35.653,9.303 36.121,9.303 37.065,8.359 37.065,7.83 36.629,7.394 v1(36.629,7.341)
PB05(RX3)_1: DL4.C U1.9 U4.26 | length 26.9
  TOP w0.15: U4.26 17.25,6.898 17.411,6.737 v1(17.411,6.615) ; v1(23.978,8.515) 23.978,9.103 DL4.C ; v1(36.563,8.151) 38.052,8.151 U1.9
  BOTTOM w0.15: v1(17.411,6.615) 18.241,7.445 22.908,7.445 v1(23.978,8.515) 24.1,8.515 24.269,8.684 24.526,8.684 24.896,9.054 27.171,9.054 28.01,9.892 31.509,9.892 32.059,9.343 32.883,9.343 33.313,9.773 33.808,9.773 34.093,10.058 34.509,10.058 34.803,9.764 34.803,9.76 35.607,8.956 35.961,8.956 36.412,8.505 36.412,8.423 36.563,8.273 v1(36.563,8.151)
PC04_1: JP3.1 U1.16 | length 7.1
  TOP w0.15: JP3.1@39.355,16.51 39.092,16.247 39.092,15.592 38.048,14.548 38.048,13.805 39.998,11.855 39.998,11.575 U1.16
PC05_1: JP3.2 U1.17 | length 9.5
  TOP w0.15: v1(38.801,9.779) 38.467,10.114 38.467,10.751 U1.17
  BOTTOM w0.15: JP3.2@36.815,16.51 36.815,13.277 38.481,11.611 38.481,11.224 38.801,10.904 v1(38.801,9.779)
PC06_1: JP3.7 U1.18 | length 21.5
  TOP w0.15: v1(37.303,11.008) 37.425,11.008 37.543,11.126 38.134,11.126 U1.18
  BOTTOM w0.15: JP3.7@24.115,16.51 24.115,15.648 24.247,15.516 25.794,15.516 25.799,15.521 28.429,15.521 28.958,14.992 33.75,14.992 34.728,14.014 35.686,14.014 38.204,11.496 38.204,11.11 38.467,10.847 38.467,10.4 38.135,10.069 37.719,10.069 37.303,10.484 v1(37.303,11.008)
PD00_1: JP2.7 U1.20 | length 25
  TOP w0.15: v1(35.915,7.797) 35.915,8.751 36.805,9.641 36.805,10.796 36.801,10.8 36.801,11.224 37.173,11.595 37.189,11.595 U1.20
  BOTTOM w0.15: JP2.7@19.035,1.27 20.543,2.778 22.691,2.778 22.882,2.968 27.611,2.968 30.021,5.378 31.268,5.378 33.592,7.703 35.137,7.703 35.231,7.797 v1(35.915,7.797)
PD01_1: JP2.6 U1.21 | length 27.8
  TOP w0.15: v1(35.4,8.315) 35.4,8.405 35.638,8.643 35.638,8.865 36.528,9.756 36.528,10.681 36.524,10.685 36.524,11.338 36.859,11.673 36.859,11.972 U1.21
  BOTTOM w0.15: JP2.6@16.495,1.27 17.573,2.348 18.867,2.348 20.531,4.013 21.95,4.013 22.718,3.245 27.496,3.245 29.906,5.655 31.153,5.655 33.477,7.98 34.443,7.98 34.779,8.315 v1(35.4,8.315)
PD02_1: JP2.5 U1.22 | length 30.1
  TOP w0.15: v1(34.936,8.895) 34.958,8.895 35.478,9.414 35.795,9.414 36.251,9.87 36.251,10.566 36.247,10.57 36.247,11.453 36.582,11.788 36.582,12.402 U1.22
  BOTTOM w0.15: JP2.5@13.955,1.27 15.01,2.325 15.825,2.325 16.187,2.687 18.795,2.687 20.398,4.29 22.065,4.29 22.832,3.522 27.382,3.522 29.792,5.932 31.038,5.932 33.363,8.257 33.902,8.257 34.065,8.42 34.462,8.42 v1(34.936,8.895)
PD03_1: JP2.4 U1.23 | length 33.8
  TOP w0.15: v1(34.301,9.556) 34.984,9.556 35.119,9.691 35.68,9.691 35.974,9.985 35.974,10.452 35.97,10.455 35.97,11.568 36.305,11.903 36.305,12.832 U1.23
  BOTTOM w0.15: JP2.4@11.415,1.27 11.612,1.27 12.56,2.217 13.022,2.217 13.267,2.462 14.414,2.462 15.281,3.329 15.871,3.329 16.236,2.964 18.68,2.964 20.283,4.567 22.18,4.567 22.947,3.799 27.176,3.799 28.316,4.939 28.316,5.877 28.649,6.209 30.923,6.209 33.248,8.534 33.787,8.534 34.301,9.048 v1(34.301,9.556)
PD04_1: JP2.10 U1.24 | length 21.3
  TOP w0.15: v1(35.472,10.193) 35.538,10.259 35.538,10.593 35.693,10.749 35.693,11.674 35.706,11.687 35.706,11.695 35.985,11.974 35.985,13.219 U1.24
  BOTTOM w0.15: JP2.10@26.655,1.27 27.422,2.037 27.855,2.037 29.768,3.95 30.61,3.95 30.706,4.046 30.719,4.046 33.821,7.149 34.694,7.149 35.09,6.753 35.663,6.753 35.75,6.839 36.837,6.839 37.131,7.133 37.131,7.505 37.342,7.716 37.342,8.473 36.093,9.723 35.942,9.723 v1(35.472,10.193)
PD05_1: JP2.11 U1.25 | length 19.8
  TOP w0.15: U1.25 35.154,13.17 35.154,12.705 34.893,12.443 v1(34.893,12.401)
  BOTTOM w0.15: JP2.11@29.195,1.27 29.195,2.132 30.459,3.396 30.459,3.407 30.821,3.769 30.834,3.769 33.936,6.872 34.579,6.872 34.975,6.476 35.778,6.476 35.864,6.562 36.951,6.562 37.408,7.019 37.408,7.39 37.619,7.601 37.619,8.588 35.974,10.233 35.974,10.401 35.97,10.405 35.97,11.323 v1(34.893,12.401)
PE00_1: JP3.14 U1.30 | length 36.4
  TOP w0.15: U1.30 33.939,10.85 v1(33.977,10.85)
  BOTTOM w0.15: JP3.14@6.35,16.51 7.439,15.421 9.074,15.421 9.079,15.416 10.714,15.416 11.226,14.904 12.273,14.904 13.966,13.21 13.966,9.017 14.639,8.344 22.314,8.344 23.686,9.716 24.005,9.716 24.211,9.716 25.188,10.693 25.982,10.693 26.054,10.621 27.158,10.621 27.591,11.054 33.651,11.054 33.855,10.85 v1(33.977,10.85)
PE01_1: JP3.15 U1.31 | length 38.2
  TOP w0.15: U1.31 32.417,11.683 33.206,10.894 33.206,10.638 v1(33.293,10.552)
  BOTTOM w0.15: JP3.15@3.81,16.51 5.176,15.144 7.885,15.144 7.89,15.139 10.599,15.139 11.111,14.627 12.158,14.627 13.689,13.096 13.689,8.902 14.525,8.067 22.429,8.067 23.801,9.439 24.119,9.439 24.326,9.439 25.303,10.416 25.867,10.416 25.939,10.344 27.273,10.344 27.345,10.416 27.358,10.416 27.666,10.723 32.8,10.723 32.893,10.631 33.213,10.631 v1(33.293,10.552)
PE02_1: JP2.1 R2.2 U1.32 | length 51.3
  TOP w0.15: v1(3.643,3.271) 3.643,3.149 3.824,2.968 3.824,1.284 JP2.1@3.81,1.27 ; v1(7.658,14.642) 7.708,14.592 8.033,14.592 8.25,14.375 R2.2 ; U1.32 32.71,10.664 32.71,10.288 v1(32.266,9.845)
  BOTTOM w0.15: v1(3.643,3.271) 3.643,3.393 3.81,3.561 3.81,3.608 4.2,3.998 6.146,3.998 7.802,5.654 7.802,9.798 8.55,10.546 8.55,13.628 7.658,14.52 v1(7.658,14.642) 7.755,14.642 7.972,14.859 10.488,14.859 10.996,14.35 12.043,14.35 13.4,12.993 13.4,8.755 14.433,7.722 22.476,7.722 23.916,9.162 24.441,9.162 24.61,9.331 27.057,9.331 27.895,10.169 31.942,10.169 v1(32.266,9.845)
PE03_1: JP3.11 U1.33 | length 20.4
  TOP w0.15: v1(29.2,13.7) 29.2,13.06 30.585,11.675 30.993,11.675 U1.33
  BOTTOM w0.15: JP3.11@13.955,16.51 14.919,15.546 16.495,15.546 16.609,15.432 17.726,15.432 18.321,14.837 22.858,14.837 23.286,14.408 26.253,14.408 26.258,14.413 27.32,14.413 27.917,13.816 28.346,13.816 28.461,13.7 v1(29.2,13.7)
PF04_1: JP3.9 U1.38 | length 22.5
  TOP w0.15: U1.38 31.585,8.112 31.585,8.612 31.528,8.67 31.528,8.873 v1(31.441,8.959)
  SIG w0.15: v1(31.441,8.959) 31.441,10.391 32.945,11.895 v1(32.945,14.192)
  BOTTOM w0.15: JP3.9@19.035,16.51 20.154,15.391 23.087,15.391 23.516,14.962 26.024,14.962 26.029,14.967 28.186,14.967 28.739,14.414 32.636,14.414 32.858,14.192 v1(32.945,14.192)
PF05_1: JP3.6 U1.39 | length 19.1
  TOP w0.15: U1.39 31.95,7.77 31.95,9.047 32.245,9.343 32.474,9.343 33.182,10.05 33.693,10.05 33.978,10.335 34.496,10.335 35.139,10.978 35.139,11.904 35.152,11.917 35.152,11.95 35.431,12.229 35.431,14.056 v1(34.972,14.516)
  BOTTOM w0.15: JP3.6@26.655,16.51 27.342,15.823 28.519,15.823 29.073,15.269 34.219,15.269 v1(34.972,14.516)
R\A\2\A\1\_\R\E\S\E\T\_1: R11.1 TP_RESETN.X U4.19 | length 37.3
  TOP w0.15: R11.1@14.625,9.45 15.341,10.167 v1(15.341,10.278) 15.363,10.278 15.635,10.55 U4.19
  TOP w0.3: R11.1 R11.1@14.625,9.45
  BOTTOM w0.15: v1(15.341,10.278) 16.42,9.2 21.995,9.2 23.342,10.547 23.66,10.547 23.867,10.547 24.844,11.524 26.326,11.524 26.398,11.452 26.814,11.452 27.44,12.079 28.445,12.079 29.071,12.705 29.566,12.705 30.297,11.974 32.689,11.974 34.172,13.457 35.393,13.457 36.801,12.049 36.801,10.749 36.805,10.745 36.805,10.577 38.45,8.932 38.45,8.4 38.75,8.1 40.466,8.1 41.808,9.442 TP_RESETN.X
R\E\S\E\T\_1: C8.2 JP2.13 JP3.3 PB1.2 R10.1 U1.40 | length 72.3
  TOP w0.15: U1.40 32.48,7.593 ; v1(32.453,8.841) 32.537,8.757 32.537,7.65 32.48,7.593 ; v1(34.147,6.37) 33.76,6.37 32.537,7.593 32.48,7.593 ; JP3.3@34.275,16.51 35.411,15.374 v1(37.953,15.374)
  TOP w0.21: R10.1 5.283,5.92 C8.2 5.283,7.332 5.464,7.513 8.551,7.513 8.9,7.862 9.539,7.862 9.827,7.574 11.985,7.574 12.169,7.758 12.169,10.7 11.985,10.885 10.9,10.885 PB1.2
  BOTTOM w0.15: v1(12.15,10.05) 13.123,9.077 13.123,8.64 14.347,7.416 15.9,7.416 17.203,6.113 17.619,6.113 18.674,7.168 23.444,7.168 25.042,8.767 27.276,8.767 28.124,9.615 30.684,9.615 30.883,9.417 30.883,8.726 31.182,8.427 32.039,8.427 v1(32.453,8.841) ; v1(34.147,6.37) 34.224,6.293 34.224,5.65 ; JP2.13@34.275,1.27 34.224,1.321 34.224,4.55 34.224,5.65 ; v1(37.953,15.374) 37.953,14.802 38.15,14.606 38.15,14.287 38.737,13.7 41.143,13.7 42.805,12.038 42.805,9.655 40.65,7.5 39.085,7.5 38.516,6.931 38.516,6.508 36.593,4.585 35.505,4.585 34.44,5.65 34.224,5.65
RA2A1_MD_1: Q1.6 Q2.3 R13.1 U4.20 | length 29.9
  TOP w0.15: v1(15.35,9.4) 15.436,9.486 15.436,9.663 15.773,10 16.025,10 U4.20 ; v1(26.606,11.954) 27.33,11.954 27.658,12.283 27.723,12.347 27.723,12.283 27.723,11.929 29.227,10.425 29.227,10.038 29.325,9.94 29.325,8.843 28.814,8.332 v1(28.814,7.692)
  TOP w0.2: R13.1 27.693,4.202 27.375,4.52 27.375,5.782 27.7,6.106 28.096,6.106 Q1.6
  BOTTOM w0.15: v1(15.35,9.4) 14.839,9.911 14.839,10.648 14.971,10.78 20.98,10.78 22.565,12.365 26.195,12.365 v1(26.606,11.954) ; v1(27.375,5.229) 26.86,5.229 26.39,5.698 26.39,6.482 27.6,7.692 v1(28.814,7.692)
UPDI_1: R12.2 U1.41 U4.48 | length 17.2
  TOP w0.15: v1(22.844,14.005) 22.844,13.6 22.894,13.55 U4.48 ; v1(28.004,13.313) 28.024,13.293 28.024,12.913 28.484,12.452 28.484,11.559 29.546,10.497 29.546,10.11 29.602,10.054 29.602,8.668 29.316,8.382 29.316,7.484 29.285,7.454 29.285,6.307 30.018,5.574 30.224,5.574 R12.2
  TOP w0.2: R12.2 31.444,5.85 U1.41
  BOTTOM w0.15: v1(22.844,14.005) 22.903,14.064 27.252,14.064 v1(28.004,13.313)
USB_D_1_N: D1.3 D-.X J1.2 U4.14 | length 22.3
  TOP w0.21: J1.2 v1@4.502,9.54 ; v1@4.728,9.58 4.914,9.394 6.321,9.394 6.324,9.397 8.176,9.397 8.65,9.871 8.65,11.437 10.193,12.98 15.6,12.98 15.67,13.05 U4.14 ; 7.35,9.43 D1.3
  BOTTOM w0.21: D-.X 1.778,13.446 1.963,13.261 2.602,13.261 2.89,12.973 3.73,12.133 3.73,9.799 4.13,9.4 4.494,9.4 4.675,9.58 v1(4.78,9.58)
USB_D_1_P: D1.2 D+.X J1.3 U4.15 | length 22.3
  TOP w0.21: J1.3 v1@4.53,8.89 ; v1(4.777,8.853) 4.957,9.034 6.47,9.034 6.473,9.037 7.35,9.037 ; D1.2 7.35,9.037 ; U4.15 15.67,12.55 15.6,12.62 10.342,12.62 9.01,11.288 9.01,9.722 8.325,9.037 7.35,9.037
  BOTTOM w0.21: D+.X 1.778,12.716 1.963,12.901 2.453,12.901 2.741,12.613 3.37,11.984 3.37,9.65 3.55,9.47 3.98,9.04 4.485,9.04 4.671,8.853 v1(4.777,8.853)
VIN: C5.2 JP2.15 R3.2 U2.16 | length 37.2
  TOP w0.2: R3.2 7.543,5.345 7.727,5.161 8.825,5.161 9.661,4.324 9.661,4.104 9.955,3.81 C5.2@10.144,3.81 ; C5.2 10.303,3.66 10.747,4.104 10.747,4.307 11.149,4.71 ; 11.199,4.71 U2.16
  TOP w0.4: C5.2@10.144,3.81 10.297,3.81 10.648,3.459 10.648,3.28 11.158,2.77 11.945,2.77 12.296,2.419 14.53,2.419 14.749,2.2 15.885,2.2 16.044,2.359 38.266,2.359 JP2.15@39.355,1.27
VUSB: D1.4 D2.A J1.1 U4.12 | length 25.9
  TOP w0.2: D1.4@5.435,10.19 5.445,10.2 6.1,10.2 6.8,10.9 7.6,10.9 11.7,15 v1(14.8,15) ; v1(16.122,14.495) 16.414,14.204 16.725,14.204 16.746,14.225 U4.12
  TOP w0.3: v1@2.608,8.293 v1(2.631,8.271) ; J1.1 D1.4@5.435,10.19 ; v1(5.266,5.077) 5.267,5.076 5.267,4.131 D2.A@5.268,4.13
  TOP w0.37: v1@2.608,8.293 2.608,9.613 3.185,10.19 J1.1
  BOTTOM w0.2: v1(14.8,15) 15.617,15 v1(16.122,14.495)
  BOTTOM w0.8: v1(2.631,8.271) 2.071,8.271 1.53,7.73 1.53,6.556 2.65,5.436 4.908,5.436 v1(5.266,5.077)
pads on no net: Fiducial_1.1 Fiducial_2.1 J1.4 TP_SWDIO.X U1.1 U1.2 U1.3 U1.7 U1.10 U1.11 U1.12 U1.13 U1.19 U1.26 U1.34 U1.35 U1.48 U2.2 U2.4 U2.5 U2.6 U2.10 U2.11 U2.15 U3.4 U4.1 U4.2 U4.4 U4.5 U4.7 U4.8 U4.10 U4.18 U4.21 U4.22 U4.23 U4.24 U4.25 U4.31 U4.32 U4.33 U4.34 U4.35 U4.36 U4.37 U4.38 U4.39 U4.40 U4.41 U4.42

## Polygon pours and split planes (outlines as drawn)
GND on SIG "GND_2" (solid, remove dead copper, pour order 6): 0,17.78 0,0 43.18,0 43.18,17.78
+5V on SIG "NONET_L-01_P-001" (solid, remove dead copper, pour order 4): 7.164,5.65 21.35,5.65 22.75,4.25 37.8,4.25 39.6,6.05 39.6,10.1 38.2,11.5 36.75,11.5 36.1,10.85 34.4,10.85 34.1,11.15 34.1,12.3 35,13.2 41.2,13.2 41.95,12.45 41.95,4.5 39.85,2.4 34.85,2.4 7.164,2.4
+3V3 on SIG "NONET_L-01_P-001" (solid, remove dead copper, pour order 1): 5.45,3 6.895,3.007 7.3,3.55 22.05,3.55 22.05,1.809 9.75,1.809 7.868,0 5,0 5,1.809 5,2.5
GND on GND "GND_2" (solid, remove dead copper, pour order 0): 0,17.78 0,0 43.18,0 43.18,17.78
GND on BOTTOM "GND_2" (solid, remove dead copper, pour order 2): 0,17.78 0,0 43.18,0 43.18,17.78
GND on TOP "GND_2" (solid, remove dead copper, pour order 5): 0,17.78 0,0 43.18,0 43.18,17.78

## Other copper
BOTTOM:
  text "5" at 0.7,3.86 h1 r270
  text "V" at 0.7,2.71 h1 r270

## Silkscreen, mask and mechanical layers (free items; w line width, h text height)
Route Tool Path:
  lines w2: -1,1 -1,0 ccw(c0,0) 0,-1 43.18,-1 ccw(c43.18,0) 44.18,0 44.18,6.5 ; -1,5 -1,13 ; -1,17 -1,17.78 cw(c0,17.78) 0,18.78 43.18,18.78 cw(c43.18,17.78) 44.18,17.78 44.18,10.5
Board:
  the board outline again, w0.1
Mechanical 7:
  lines w0.1: 1.193,11.811 1.778,11.811 ; 1.193,14.351 1.778,14.351 ; 1.778,11.226 1.778,11.811 ; 1.778,12.396 1.778,11.811 ; 1.778,13.766 1.778,14.351 ; 1.778,14.936 1.778,14.351 ; 2.363,11.811 1.778,11.811 ; 2.363,14.351 1.778,14.351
